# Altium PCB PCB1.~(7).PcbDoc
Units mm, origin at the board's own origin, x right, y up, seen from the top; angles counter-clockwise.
Board outline 152.4 x 101.6 mm, 2 copper layers (Top Layer, Bottom Layer); 19 components, 17 nets, 64 pads, 2 vias.
Unrouted connection lines stored in the file: 24.
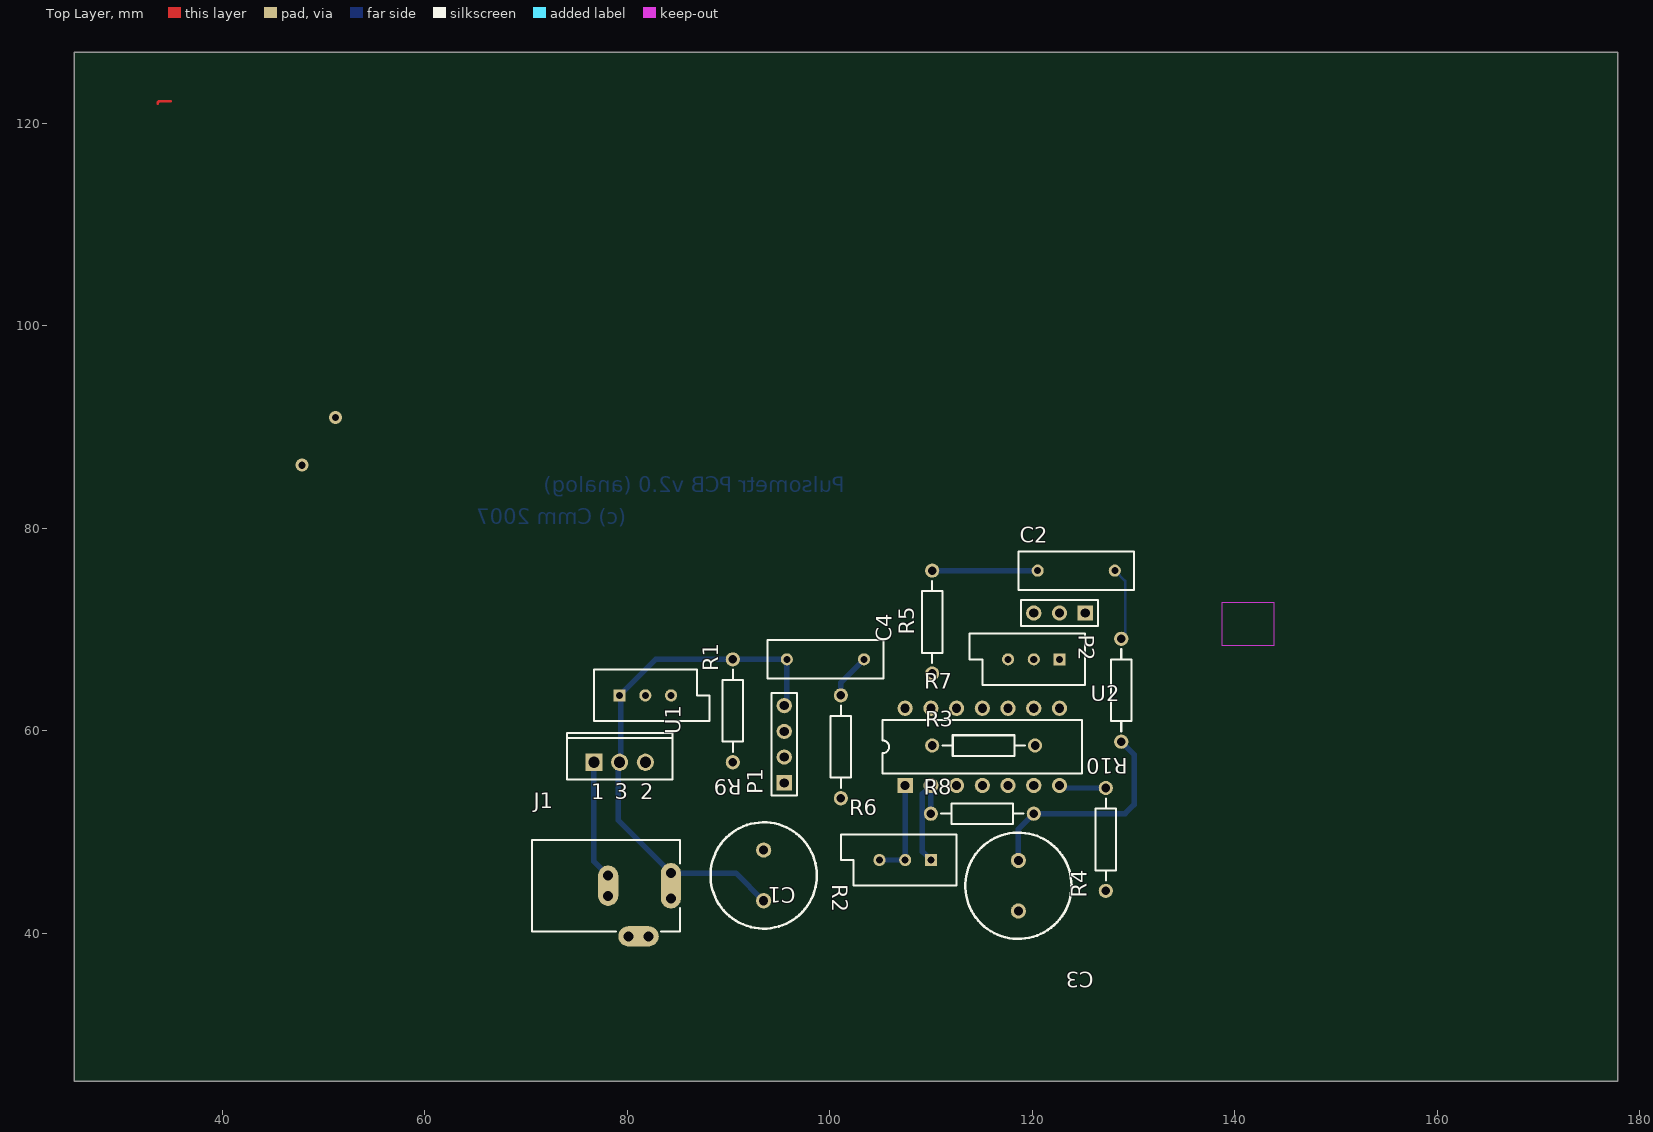
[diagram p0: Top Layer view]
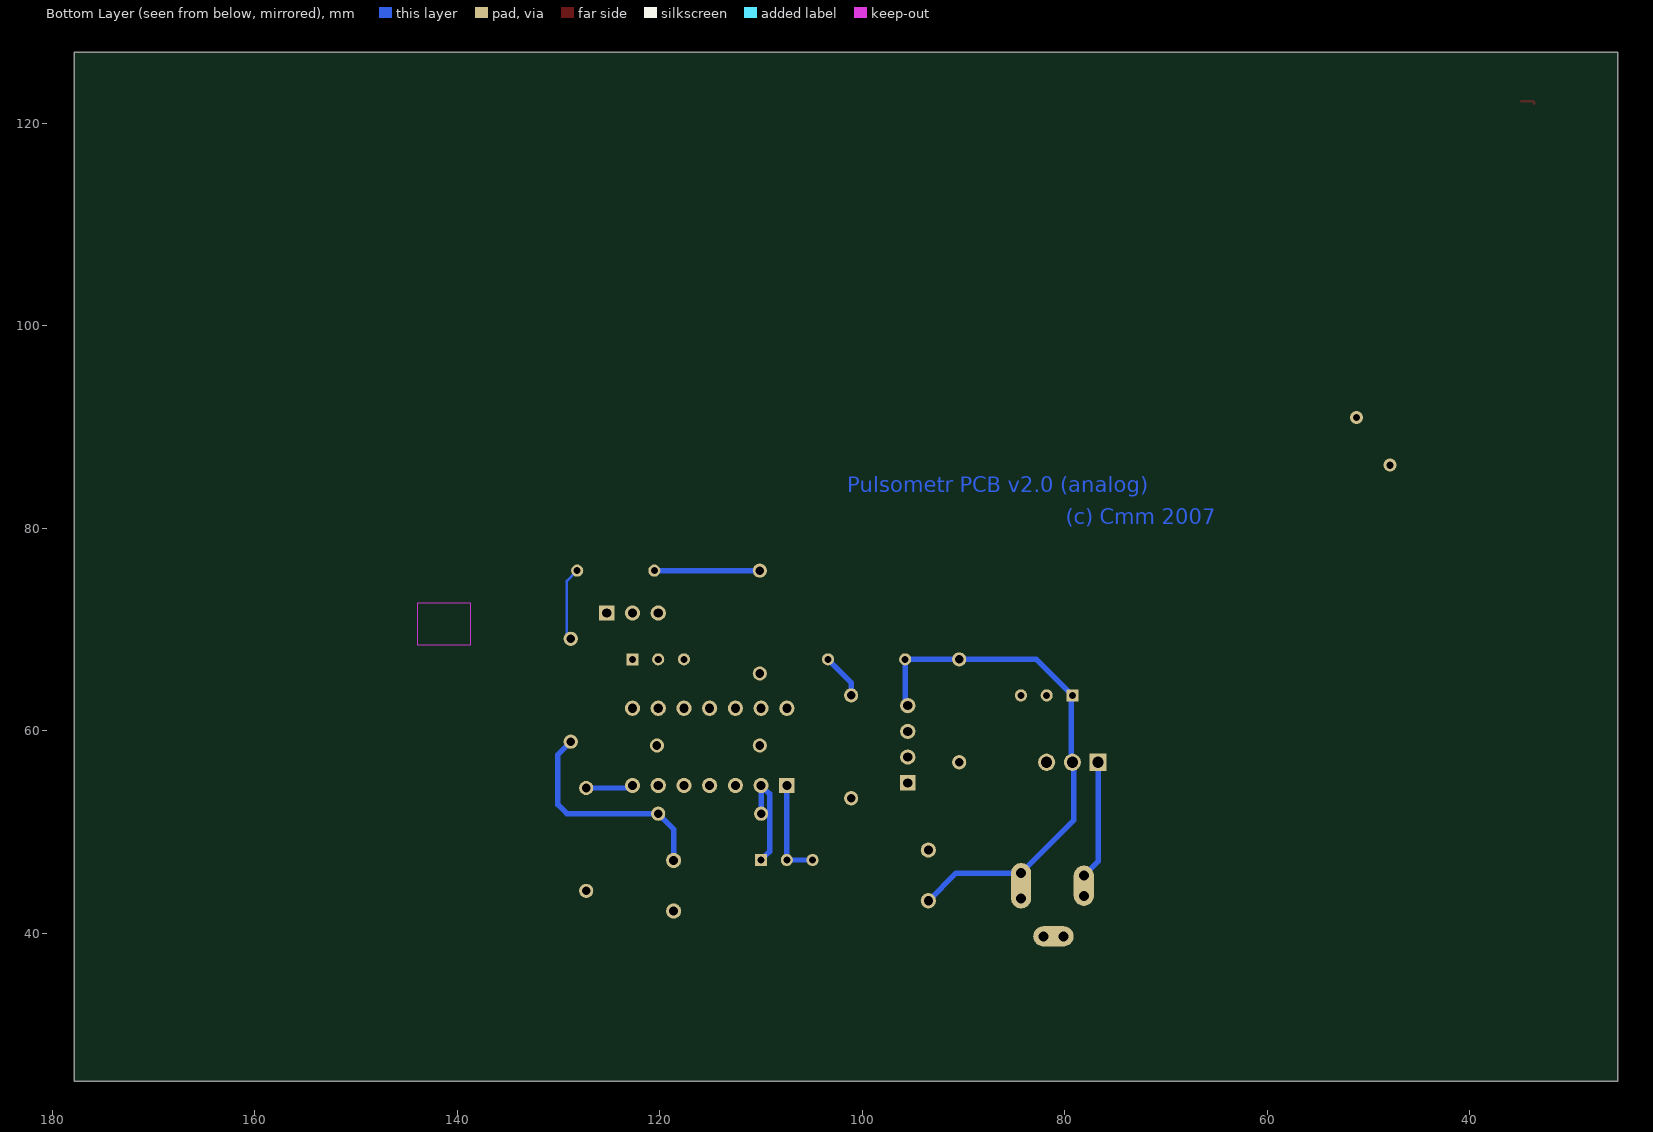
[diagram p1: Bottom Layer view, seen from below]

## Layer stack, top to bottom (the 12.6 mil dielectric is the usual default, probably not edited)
Top Layer: signal copper 0.0356
Dielectric: dielectric 0.32, FR-4, Dk 4.8
Bottom Layer: signal copper 0.0356

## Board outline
25.4,25.4 177.8,25.4 177.8,127 25.4,127

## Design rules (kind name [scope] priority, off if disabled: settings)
Clearance [All] p1: gap=0.254
ComponentClearance [All] p1: gap=0.254 collisioncheckmode=3 verticalgap=0.254
PolygonConnect [All] p1: connectstyle=Relief reliefconductorwidth=0.254 reliefentries=4 polygonreliefangle="90 Angle"
RoomDefinition Sheet1 [InComponentClass('Sheet1')] p1: confinementstyle=ConfineIn formatcopy=TRUE lockcomponents=FALSE outline 59.563,36.83 133.604,36.83 133.604,78.867 59.563,78.867
RoutingVias [All] p1: holewidth=0.711 width=2 viastyle="Through Hole" minholewidth=0.711 minwidth=1.27 maxholewidth=0.711 maxwidth=2.27
SolderMaskExpansion [All] p1: expansion=0.102
TestPointUsage [All] p1: valid=0 allowmultiple=FALSE
Testpoint [All] p1: side=15 testpointundercomponent=TRUE minsize=1.016 maxsize=2.54 preferedsize=1.524 minholesize=0 maxholesize=1.016 preferedholesize=0.813 testpointgrid=0.025 style=1023 order=0123456789
Width [All] p1: maxlimit=1254 minlimit=0.254 preferedwidth=0.254 toplayer_maxwidth=1.254 toplayer_prefwidth=0.54 bottomlayer_prefwidth=0.54 minimp=50.000000 maximp=50.000000 favimp=50.000000
18 further rules are at their usual default settings.

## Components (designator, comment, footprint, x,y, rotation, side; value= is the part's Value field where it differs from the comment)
C1 "Cap Pol1" RB5-10.5 93.472,45.72 r90 top
C2 "Cap" RAD-0.3 124.333,75.819 r180 top
C3 "Cap Pol1" RB5-10.5 118.618,44.704 r90 top
C4 "Cap" RAD-0.3 99.568,67.056 r0 top
J1 "PWR2.5" KLD-0202 70.612,44.704 r0 top
P1 "Header 4" HDR1X4 95.504,54.864 r90 top
P2 "Header 3" HDR1X3 125.222,71.628 r180 top
R1 "RPot" VR5 81.788,63.5 r0 top
R2 "RPot" VR5 107.442,47.244 r180 top
R3 "Res2" AXIAL-0.4 115.189,58.547 r180 top
R4 "Res2" AXIAL-0.4 127.254,49.276 r90 top
R5 "Res2" AXIAL-0.4 110.109,70.739 r270 top
R6 "Res2" AXIAL-0.4 101.092,58.42 r270 top
R7 "RPot" VR5 120.142,67.056 r180 top
R8 "Res2" AXIAL-0.4 115.062,51.816 r0 top
R9 "Res2" AXIAL-0.4 90.424,61.976 r270 top
R10 "Res2" AXIAL-0.4 128.778,64.008 r270 top
U1 "L7812ABV" TO220ABN 79.248,56.896 r0 top
U2 "LM324AN" N14A 115.062,58.42 r0 top

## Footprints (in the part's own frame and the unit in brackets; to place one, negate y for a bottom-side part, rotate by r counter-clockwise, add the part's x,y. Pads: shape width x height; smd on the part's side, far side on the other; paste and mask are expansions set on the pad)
AXIAL-0.4 [mm] "Resistor; 2 Leads"
  round 1.4 hole 0.85: 1(-5.08,0) 2(5.08,0)
  silkscreen extent -4.06,-1.02 4.06,1.02
HDR1X3 [mm] "Connector; Header; 3 Position"
  rect 1.5x1.5 hole 0.9: 1(0,0)
  round 1.5 hole 0.9: 2(2.54,0) 3(5.08,0)
  silkscreen extent -1.27,-1.27 6.35,1.27
HDR1X4 [mm] "Connector; Header; 4 Position"
  rect 1.5x1.5 hole 0.9: 1(0,0)
  round 1.5 hole 0.9: 2(2.54,0) 3(5.08,0) 4(7.62,0)
  silkscreen extent -1.27,-1.27 8.89,1.27
KLD-0202 [mm] "DC Power Jack, 2.5mm, KLD Series, PCB Mount"
  oval 2x4.5 all layers, no hole: 1(13.7,0)
  round 1.5 hole 1: 1A(13.7,-1.25) 1B(13.7,1.25) 2A(7.5,-1) 2B(7.5,1) 3A(9.5,-5) 3B(11.5,-5)
  oval 2x4 all layers, no hole: 2(7.5,0)
  oval 4x2 all layers, no hole: 3(10.5,-5)
  silkscreen extent 0,-4.5 14.6,4.5
N14A [mm] "DIP; 14 Leads; Row Spacing 7.62 mm; Pitch 2.54 mm"
  rect 1.5x1.5 hole 0.9: 1(-7.62,-3.81)
  round 1.5 hole 0.9: 2(-5.08,-3.81) 3(-2.54,-3.81) 4(0,-3.81) 5(2.54,-3.81) 6(5.08,-3.81) 7(7.62,-3.81) 8(7.62,3.81) 9(5.08,3.81) 10(2.54,3.81) 11(0,3.81) 12(-2.54,3.81) 13(-5.08,3.81) 14(-7.62,3.81)
  silkscreen extent -9.85,-2.65 9.85,2.65
RAD-0.3 [mm] "Capacitor; 2 Leads"
  round 1.2 hole 0.7: 1(-3.81,0) 2(3.81,0)
  silkscreen extent -5.71,-1.91 5.71,1.91
RB5-10.5 [mm] "Motor, General Kind; 2 Leads"
  round 1.5 hole 0.9: 1(-2.5,0) 2(2.5,0)
  silkscreen extent -5.25,-5.25 5.25,5.25
TO220ABN [mm] "TO, Thru-Hole, Vertical, Heatsink Mounted; 3 In-Line Leads; Pitch 2.54 mm; Pin sequence 1, 3, 2"
  rect 1.7x1.7 hole 1.1: 1(-2.54,0)
  round 1.7 hole 1.1: 2(2.54,0) 3(0,0)
  silkscreen extent -5.2,-1.7 5.2,2.9
VR5 [mm] "Potentiometer; 3 Leads"
  rect 1.2x1.2 hole 0.7: 1(-2.54,0)
  round 1.2 hole 0.7: 2(0,0) 3(2.54,0)
  silkscreen extent -5.08,-2.54 6.35,2.54

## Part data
C1 C3: "Polarized Capacitor (Radial)"
C2 C4: "Capacitor"
J1: "Low Voltage Power Supply Connector"
P1: "Header, 4-Pin"
P2: library part "Header 2", "Header, 2-Pin"
R1 R2 R7: "Potentiometer"
R3 R4 R5 R6 R8 R9 R10: "Resistor"
U1: "Precision 1A Regulator"
U2: "Low-Power Quad Operational Amplifier"

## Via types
v1: diameter 1.27, hole 0.711, Top Layer to Bottom Layer, 2 vias

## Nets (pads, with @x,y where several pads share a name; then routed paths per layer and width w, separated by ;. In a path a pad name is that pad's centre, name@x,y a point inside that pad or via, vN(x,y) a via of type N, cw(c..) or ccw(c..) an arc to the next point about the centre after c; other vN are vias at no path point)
+5: C1.2 P1.1 P2.1 R1.2 U1.2 U2.4
GND: C1.1 C3.2 C4.1 J1.1 J1.1A J1.1B P1.4 P2.3 R1.1 R7.2 R8.2 R9.1 R10.2 U1.3 U2.11 | length 75
  Bottom Layer w0.54: U1.3@79.121,57.023 79.121,56.896 79.121,51.145 J1.1B 90.738,45.954 C1.1 ; U1.3@79.375,57.023 79.375,63.373 R1.1 82.804,67.056 R9.1 C4.1 ; P1.4 95.758,62.738 C4.1@95.758,66.802 ; C3.2 118.618,50.292 R8.2 129.159,51.816 130.048,52.705 130.048,57.658 R10.2 128.651,59.055 R10.2@128.524,59.055
NetC2_1: C2.1 R10.1 U2.5 | length 7.2
  Bottom Layer w0.254: C2.1 129.159,74.803 R10.1@129.159,69.088
NetC2_2: C2.2 R5.1 | length 10.4
  Bottom Layer w0.54: R5.1 C2.2
NetC3_1: C3.1 R4.1 U2.3
NetC4_2: C4.2 R6.1 U2.12 | length 4.5
  Bottom Layer w0.54: R6.1 101.092,64.77 C4.2
NetJ1_3: J1.3 J1.3A J1.3B
NetP1_2: P1.2 R6.2 R9.2
NetP1_3: P1.3 R1.3
NetP2_2: P2.2 R7.1 U2.8
NetR2_1: R2.1 R8.1 U2.2 | length 10.9
  Bottom Layer w0.54: R2.1 109.144,48.082 109.144,51.816 109.144,53.772 U2.2 R8.1
NetR2_2: R2.2 R2.3 R3.2 U2.1 | length 9.9
  Bottom Layer w0.54: R2.3 R2.2 U2.1
NetR3_1: R3.1 U2.9
NetR4_2: R4.2 U2.6 U2.7 | length 4.7
  Bottom Layer w0.54: U2.7 122.936,54.356 R4.2
NetR5_2: R5.2 U2.13 U2.14
NetR7_3: R7.3 U2.10
VCC: J1.2 J1.2A J1.2B U1.1 | length 11.8
  Bottom Layer w0.54: U1.1 76.708,47.108 J1.2B
copper on no net: | length 1.4
  Top Layer w0.254: 33.655,121.92 33.655,122.047 33.782,122.174 34.925,122.174
  other v1: 47.879,86.233 51.181,90.932

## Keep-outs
Keep-Out Layer:
  rectangle: 138.684,68.453 143.891,72.644

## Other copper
Bottom Layer:
  text "Pulsometr PCB v2.0 (analog)" at 101.473,83.566 h1.52
  text "(c) Cmm 2007" at 79.883,80.391 h1.52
